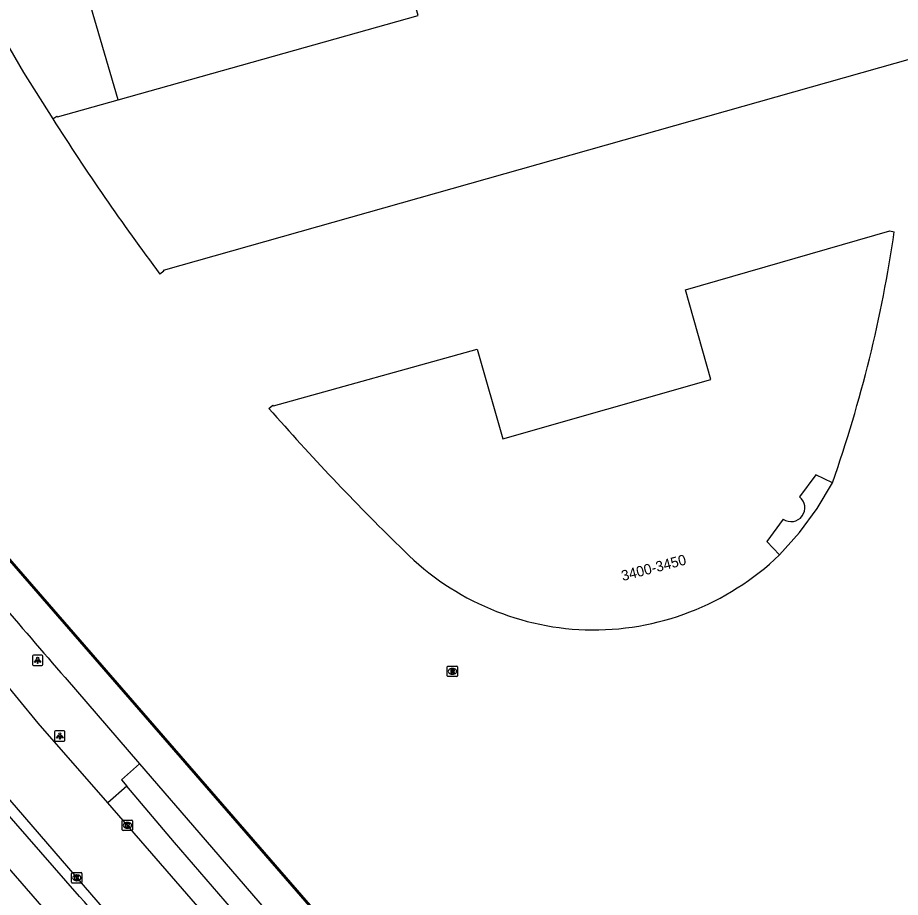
# Model space of a CAD drawing. Extents: x 155018 to 156648, y 383980 to 385733.
# Drawn here: x 156123 to 156208, y 384480.5 to 384565.1 of the extents above; entities that cross this region are included whole.
import ezdxf

# ---------------------------------------------------------------- set-up
doc = ezdxf.new("R2010")
doc.units = 0
for name, color, linetype in [('IMGEO_Fietspad_gesloten', 7, 'Continuous'), ('IMGEO_Fietspad_open', 7, 'Continuous'), ('IMGEO_Kolk', 7, 'Continuous'), ('IMGEO_Lichtpunt', 7, 'Continuous'), ('IMGEO_Lijnafwatering', 7, 'Continuous'), ('IMGEO_OVBaan_gesloten', 7, 'Continuous'), ('IMGEO_Pand', 7, 'Continuous'), ('IMGEO_Pand_nummerreeks', 7, 'Continuous'), ('IMGEO_Pand_overbouw', 7, 'Continuous'), ('IMGEO_Rijbaan_lokaal_gesloten', 7, 'Continuous'), ('IMGEO_Rijbaan_lokaal_open', 7, 'Continuous'), ('IMGEO_Rioolput', 7, 'Continuous')]:
    doc.layers.add(name, color=color, linetype=linetype)

msp = doc.modelspace()

# ---------------------------------------------------------------- linework, layer by layer
at = {"layer": 'IMGEO_Fietspad_gesloten'}
msp.add_lwpolyline([(156145.448, 384477.274), (156138.128, 384485.73), (156133.53, 384491.15)], dxfattribs=at)
at = {"layer": 'IMGEO_Fietspad_open'}
for points in [[(156128.992, 384480.539), (156115.39, 384496.107), (156095.397, 384517.924)], [(156103.806, 384503.671), (156107.304, 384500), (156112.344, 384494.525), (156112.781, 384494.01), (156141.033, 384461.516)]]:
    msp.add_lwpolyline(points, dxfattribs=at)
msp.add_arc((155197.593, 383660.364), 1241.044, 40.338002, 41.366653, dxfattribs=at)
at = {"layer": 'IMGEO_Kolk'}
for p, q in [((156133.093, 384486.963), (156133.093, 384487.815)), ((156133.168, 384487.889), (156134.02, 384487.889)), ((156133.581, 384487.669), (156133.606, 384487.669)), ((156134.094, 384487.815), (156134.094, 384486.963)), ((156134.02, 384486.889), (156133.168, 384486.889)), ((156133.604, 384487.109), (156133.579, 384487.109)), ((156128.211, 384481.914), (156128.211, 384482.766)), ((156128.286, 384482.84), (156129.138, 384482.84)), ((156128.722, 384482.06), (156128.697, 384482.06)), ((156128.699, 384482.62), (156128.724, 384482.62)), ((156129.212, 384482.766), (156129.212, 384481.914)), ((156129.138, 384481.84), (156128.286, 384481.84))]:
    msp.add_line(p, q, dxfattribs=at)
for points in [[(156133.093, 384486.963), (156133.093, 384487.815)], [(156133.168, 384487.889), (156134.02, 384487.889)], [(156133.414, 384487.589), (156133.537, 384487.589), (156133.537, 384487.438), (156133.667, 384487.589), (156133.831, 384487.589), (156133.685, 384487.438), (156133.838, 384487.189), (156133.686, 384487.189), (156133.601, 384487.353), (156133.537, 384487.286), (156133.537, 384487.189), (156133.414, 384487.189), (156133.414, 384487.589)], [(156134.094, 384487.815), (156134.094, 384486.963)], [(156134.02, 384486.889), (156133.168, 384486.889)], [(156128.211, 384481.914), (156128.211, 384482.766)], [(156128.286, 384482.84), (156129.138, 384482.84)], [(156128.532, 384482.54), (156128.655, 384482.54), (156128.655, 384482.389), (156128.785, 384482.54), (156128.949, 384482.54), (156128.803, 384482.389), (156128.956, 384482.14), (156128.804, 384482.14), (156128.719, 384482.304), (156128.655, 384482.237), (156128.655, 384482.14), (156128.532, 384482.14), (156128.532, 384482.54)], [(156129.212, 384482.766), (156129.212, 384481.914)], [(156129.138, 384481.84), (156128.286, 384481.84)]]:
    msp.add_lwpolyline(points, dxfattribs=at)
for centre, start, end in [((156133.17, 384487.813), 91.55205, 178.44795), ((156133.17, 384487.813), 91.55205, 178.44795), ((156134.018, 384487.813), 1.55205, 88.44795), ((156134.018, 384487.813), 1.55205, 88.44795), ((156133.17, 384486.965), 181.55205, 268.44795), ((156133.17, 384486.965), 181.55205, 268.44795), ((156134.018, 384486.965), 271.55205, 358.44795), ((156134.018, 384486.965), 271.55205, 358.44795), ((156128.288, 384482.764), 91.55205, 178.44795), ((156128.288, 384482.764), 91.55205, 178.44795), ((156129.136, 384482.764), 1.55205, 88.44795), ((156129.136, 384482.764), 1.55205, 88.44795), ((156128.288, 384481.916), 181.55205, 268.44795), ((156128.288, 384481.916), 181.55205, 268.44795), ((156129.136, 384481.916), 271.55205, 358.44795), ((156129.136, 384481.916), 271.55205, 358.44795)]:
    msp.add_arc(centre, 0.0765, start, end, dxfattribs=at)
for centre, major_axis, ratio, start_param, end_param in [((156133.58, 384487.389), (-0.387, 0.002), 0.722429, 4.712389, 7.853982), ((156133.605, 384487.389), (-0.39, 0.002), 0.717154, 1.570796, 4.712389), ((156128.698, 384482.34), (-0.387, 0.002), 0.722429, 4.712389, 7.853982), ((156128.723, 384482.34), (-0.39, 0.002), 0.717154, 1.570796, 4.712389)]:
    msp.add_ellipse(centre, major_axis=major_axis, ratio=ratio, start_param=start_param, end_param=end_param, dxfattribs=at)
at = {"layer": 'IMGEO_Lichtpunt'}
for p, q in [((156124.451, 384503.675), (156124.451, 384502.868)), ((156124.451, 384503.675), (156124.451, 384502.868)), ((156125.353, 384503.77), (156124.545, 384503.77)), ((156125.353, 384503.77), (156124.545, 384503.77)), ((156125.447, 384502.868), (156125.447, 384503.675)), ((156125.447, 384502.868), (156125.447, 384503.675)), ((156124.545, 384502.774), (156125.353, 384502.774)), ((156124.545, 384502.774), (156125.353, 384502.774)), ((156127.485, 384496.491), (156126.677, 384496.491)), ((156127.485, 384496.491), (156126.677, 384496.491)), ((156126.583, 384496.396), (156126.583, 384495.589)), ((156126.583, 384496.396), (156126.583, 384495.589)), ((156127.579, 384495.589), (156127.579, 384496.396)), ((156127.579, 384495.589), (156127.579, 384496.396)), ((156126.677, 384495.495), (156127.485, 384495.495)), ((156126.677, 384495.495), (156127.485, 384495.495))]:
    msp.add_line(p, q, dxfattribs=at)
for points in [[(156124.825, 384503.339), (156124.864, 384503.311), (156124.676, 384503.049), (156124.638, 384503.076), (156124.825, 384503.339)], [(156124.927, 384503.291), (156124.974, 384503.291), (156124.974, 384502.969), (156124.927, 384502.969), (156124.927, 384503.291)], [(156125.037, 384503.311), (156125.075, 384503.338), (156125.262, 384503.076), (156125.223, 384503.048), (156125.037, 384503.311)], [(156126.957, 384496.06), (156126.996, 384496.032), (156126.808, 384495.77), (156126.77, 384495.797), (156126.957, 384496.06)], [(156127.059, 384496.012), (156127.106, 384496.012), (156127.106, 384495.69), (156127.059, 384495.69), (156127.059, 384496.012)], [(156127.169, 384496.032), (156127.207, 384496.059), (156127.394, 384495.797), (156127.355, 384495.769), (156127.169, 384496.032)]]:
    msp.add_lwpolyline(points, dxfattribs=at)
for centre in [(156124.95, 384503.473), (156127.082, 384496.194)]:
    msp.add_circle(centre, 0.0994, dxfattribs=at)
for centre, start, end in [((156124.545, 384503.675), 90, 180), ((156124.545, 384503.675), 90, 180), ((156125.353, 384503.675), 0, 90), ((156125.353, 384503.675), 0, 90), ((156124.545, 384502.868), 180, 270), ((156124.545, 384502.868), 180, 270), ((156125.353, 384502.868), 270, 0), ((156125.353, 384502.868), 270, 360), ((156126.677, 384496.396), 90, 180), ((156126.677, 384496.396), 90, 180), ((156127.485, 384496.396), 0, 90), ((156127.485, 384496.396), 0, 90), ((156126.677, 384495.589), 180, 270), ((156126.677, 384495.589), 180, 270), ((156127.485, 384495.589), 270, 0), ((156127.485, 384495.589), 270, 360)]:
    msp.add_arc(centre, 0.0946, start, end, dxfattribs=at)
at = {"layer": 'IMGEO_Lijnafwatering'}
for points in [[(156134.285, 384499.027), (156121.646, 384513.59)], [(156146.924, 384484.465), (156134.285, 384499.027)], [(156159.563, 384469.902), (156146.924, 384484.465)]]:
    msp.add_lwpolyline(points, dxfattribs=at)
at = {"layer": 'IMGEO_OVBaan_gesloten'}
for points in [[(156131.708, 384489.55), (156125.015, 384497.231), (156121.184, 384501.846), (156102.61, 384525.457)], [(156108.607, 384505.838), (156115.176, 384497.989), (156148.3, 384459.668), (156155.897, 384450.049), (156162.984, 384441.307), (156173.602, 384428.736), (156177.731, 384423.954)], [(156143.734, 384475.688), (156136.368, 384484.205), (156131.708, 384489.55)]]:
    msp.add_lwpolyline(points, dxfattribs=at)
at = {"layer": 'IMGEO_Pand'}
for points in [[(156126.401, 384555.377), (156126.797, 384555.633), (156126.852, 384555.549), (156132.689, 384557.19), (156161.572, 384565.312), (156157.372, 384580.185), (156128.376, 384572.021), (156118.785, 384569.321), (156118.835, 384569.234), (156118.42, 384568.993)], [(156209.58, 384560.999), (156209.13, 384561.067), (156209.145, 384561.166), (156137.035, 384540.79), (156137.095, 384540.71), (156136.721, 384540.431)], [(156147.212, 384527.497), (156147.586, 384527.824), (156147.657, 384527.741), (156167.245, 384533.202), (156169.705, 384524.585), (156189.753, 384530.272), (156187.316, 384538.912), (156206.969, 384544.578), (156207.395, 384544.505)], [(156201.441, 384520.353), (156199.849, 384521.115), (156198.279, 384518.984)], [(156196.711, 384516.847), (156195.134, 384514.69), (156196.348, 384513.409)]]:
    msp.add_lwpolyline(points, dxfattribs=at)
for centre, radius, start, end in [((156322.625, 384679.831), 232.363, 212.38468, 216.86437), ((156080.26, 384563.037), 128.479, 340.59617, 351.70676), ((156326.366, 384684.619), 238.293, 221.2516, 225.65352), ((156197.461, 384517.94), 1.326, 235.55375, 51.90836), ((156178.608, 384532.224), 26.043, 223.76456, 267.91581), ((156178.395, 384532.114), 25.926, 268.37713, 313.8244)]:
    msp.add_arc(centre, radius, start, end, dxfattribs=at)
at = {"layer": 'IMGEO_Pand_overbouw'}
msp.add_lwpolyline([(156118.42, 384568.993), (156120.94, 384564.373), (156123.601, 384559.833), (156126.401, 384555.377), (156126.797, 384555.633), (156126.852, 384555.549), (156132.689, 384557.19), (156128.376, 384572.021), (156118.785, 384569.321), (156118.835, 384569.234)], close=True, dxfattribs=at)
for points in [[(156201.441, 384520.353), (156199.849, 384521.115), (156198.279, 384518.984)], [(156196.711, 384516.847), (156195.134, 384514.69), (156196.348, 384513.409), (156198.273, 384515.552), (156199.976, 384517.874), (156201.441, 384520.353)]]:
    msp.add_lwpolyline(points, dxfattribs=at)
msp.add_arc((156197.461, 384517.94), 1.326, 235.55375, 51.90836, dxfattribs=at)
at = {"layer": 'IMGEO_Rijbaan_lokaal_gesloten'}
for points in [[(156182.48, 384458.856), (156182.449, 384458.923), (156179.774, 384458.427), (156173.436, 384456.485), (156173.267, 384455.967), (156172.915, 384455.68), (156172.771, 384455.862), (156172.857, 384455.946), (156163.051, 384466.066), (156121.442, 384514.007)], [(156127.591, 384501.608), (156134.758, 384493.306)], [(156134.758, 384493.306), (156141.072, 384485.993), (156159.115, 384465.116), (156164.117, 384459.818), (156170.407, 384453.46), (156171.364, 384452.62)]]:
    msp.add_lwpolyline(points, dxfattribs=at)
msp.add_arc((156448.046, 384782.734), 426.29, 218.5693, 221.25957, dxfattribs=at)
at = {"layer": 'IMGEO_Rijbaan_lokaal_open'}
for points in [[(156134.758, 384493.306), (156133.008, 384491.769), (156133.53, 384491.15)], [(156133.53, 384491.15), (156131.708, 384489.55)]]:
    msp.add_lwpolyline(points, dxfattribs=at)
at = {"layer": 'IMGEO_Rioolput'}
for p, q in [((156164.367, 384501.779), (156164.367, 384502.631)), ((156164.442, 384502.705), (156165.294, 384502.705)), ((156164.855, 384502.485), (156164.88, 384502.485)), ((156165.368, 384502.631), (156165.368, 384501.779)), ((156165.294, 384501.705), (156164.442, 384501.705)), ((156164.878, 384501.925), (156164.853, 384501.925))]:
    msp.add_line(p, q, dxfattribs=at)
for points in [[(156164.367, 384501.779), (156164.367, 384502.631)], [(156164.442, 384502.705), (156165.294, 384502.705)], [(156165.368, 384502.631), (156165.368, 384501.779)], [(156165.294, 384501.705), (156164.442, 384501.705)], [(156164.956, 384502.403), (156164.704, 384502.405), (156164.704, 384502.005)], [(156164.704, 384502.005), (156164.828, 384502.005), (156164.828, 384502.167), (156164.839, 384502.167)], [(156164.882, 384502.324), (156164.828, 384502.324), (156164.828, 384502.243)], [(156164.828, 384502.243), (156164.88, 384502.243)], [(156164.886, 384502.138), (156164.957, 384502.005), (156165.097, 384502.005), (156165.032, 384502.131)]]:
    msp.add_lwpolyline(points, dxfattribs=at)
for centre, radius, start, end in [((156164.444, 384502.629), 0.0765, 91.55205, 178.44795), ((156164.444, 384502.629), 0.0765, 91.55205, 178.44795), ((156165.292, 384502.629), 0.0765, 1.55205, 88.44795), ((156165.292, 384502.629), 0.0765, 1.55205, 88.44795), ((156164.444, 384501.781), 0.0765, 181.55205, 268.44795), ((156164.444, 384501.781), 0.0765, 181.55205, 268.44795), ((156164.838, 384502.114), 0.0533, 26.02933, 88.69889), ((156164.864, 384502.432), 0.19, 274.7715, 282.96867), ((156164.888, 384502.228), 0.0964, 77.00612, 93.18647), ((156164.902, 384502.285), 0.0378, 276.66336, 79.67722), ((156164.955, 384502.293), 0.109, 350.36119, 89.41601), ((156164.953, 384502.293), 0.112, 277.58423, 350.98172), ((156164.937, 384502.078), 0.108, 29.51342, 73.79051), ((156165.292, 384501.781), 0.0765, 271.55205, 358.44795), ((156165.292, 384501.781), 0.0765, 271.55205, 358.44795)]:
    msp.add_arc(centre, radius, start, end, dxfattribs=at)
for centre, major_axis, ratio, start_param, end_param in [((156164.854, 384502.205), (-0.387, 0.002), 0.722429, 4.712389, 7.853982), ((156164.879, 384502.205), (-0.39, 0.002), 0.717154, 1.570796, 4.712389)]:
    msp.add_ellipse(centre, major_axis=major_axis, ratio=ratio, start_param=start_param, end_param=end_param, dxfattribs=at)

# ---------------------------------------------------------------- texts
at = {"layer": 'IMGEO_Pand_nummerreeks'}
msp.add_text('3400-3450', height=1, rotation=14.65581, dxfattribs=at).set_placement((156181.268, 384510.889))

doc.saveas('drawing.dxf')
